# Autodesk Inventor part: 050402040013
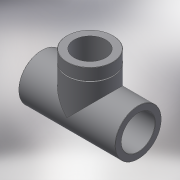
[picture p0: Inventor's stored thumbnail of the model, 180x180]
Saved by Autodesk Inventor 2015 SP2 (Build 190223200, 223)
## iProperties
Created: 2017-10
Part Number: 050402040013
Material: Generic
Description: PLASSON TEE THR-CEM REINF. P 40-1.1/4"
Document SubType Name: Modeling
Designer: KIM
Density: 1 g/cm^3
Appearance: Default
Author: KIM
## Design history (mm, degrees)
derived "057402.ipt"
feature "Solid1::057402.ipt"
feature "Solid2::057402.ipt"
tag "TaggingFeature1"
body "Solid1"
other parameters: "d0" = 98, "d1" = 48, "d2" = 26, "d5" = 35.0568, "d7" = 0.38952, "d8" = 26, "d9" = 49, "d10" = 48, "d15" = 0, "d18" = 38.952, "d24" = 0.38952, "d30" = 38.952, "d31" = 22, "d32" = 0, "d33" = 35.0568, "d35" = 0, "d37" = 0.5, "d38" = 0.5, "d39" = 12.25, "d40" = 48, "G_" = 38.952, "E_" = 48, "H_" = 98, "lt_" = 22, "l_" = 26, "h_" = 49
